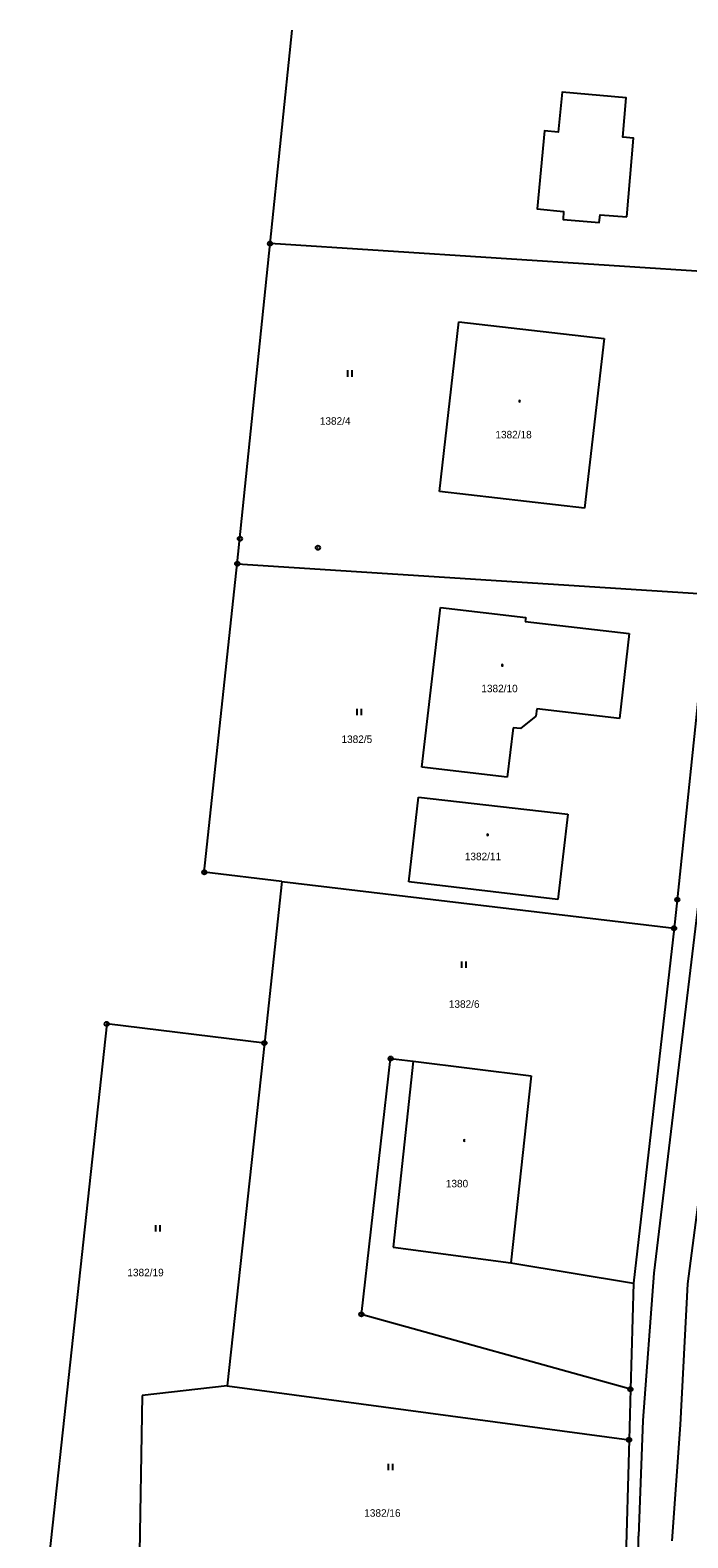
# Model space of a CAD drawing. Extents: x -454285 to -453563, y -1108687 to -1108249.
# Drawn here: x -454197.6 to -454136.3, y -1108463.6 to -1108323 of the extents above; entities that cross this region are included whole.
import ezdxf

# ---------------------------------------------------------------- set-up
doc = ezdxf.new("R2010")
doc.units = 0
for name, color, linetype in [('1', 7, 'Continuous'), ('14', 7, 'Continuous'), ('15', 7, 'Continuous'), ('2', 7, 'Continuous'), ('23', 7, 'Continuous'), ('25', 7, 'Continuous'), ('28', 7, 'Continuous')]:
    doc.layers.add(name, color=color, linetype=linetype)

# ---------------------------------------------------------------- blocks, each defined once
blk = doc.blocks.new('Z402')
for start, end in [(0, 180), (180, 0)]:
    blk.add_arc((0, 0), 0.15, start, end)
blk = doc.blocks.new('Z105')
for radius in [0.5, 0.01]:
    blk.add_circle((0, 0), radius)
blk = doc.blocks.new('Z3060')
for p, q in [((-0.5, 1.5), (-0.5, 0)), ((0.5, 1.5), (0.5, 0))]:
    blk.add_line(p, q)

msp = doc.modelspace()

# ---------------------------------------------------------------- linework, layer by layer
at = {"layer": '1'}
for p, q in [((-454175.21, -1108342.89), (-454173.16, -1108322.99)), ((-454178.27, -1108372.74), (-454175.21, -1108342.89)), ((-454131.27, -1108345.73), (-454175.21, -1108342.89)), ((-454159.44, -1108365.99), (-454157.62, -1108350.19)), ((-454157.62, -1108350.19), (-454144.08, -1108351.75)), ((-454144.08, -1108351.75), (-454145.93, -1108367.55)), ((-454145.93, -1108367.55), (-454159.44, -1108365.99)), ((-454178.27, -1108372.74), (-454134.34, -1108375.58)), ((-454161.07, -1108391.71), (-454159.33, -1108376.82)), ((-454159.33, -1108376.82), (-454151.39, -1108377.74)), ((-454151.39, -1108377.74), (-454151.44, -1108378.11)), ((-454151.44, -1108378.11), (-454141.75, -1108379.24)), ((-454141.75, -1108379.24), (-454142.65, -1108387.16)), ((-454134.9, -1108381.08), (-454137.27, -1108404.06)), ((-454150.36, -1108386.27), (-454150.44, -1108386.95)), ((-454142.65, -1108387.16), (-454150.36, -1108386.27)), ((-454152.56, -1108388.03), (-454153.12, -1108392.64)), ((-454151.88, -1108388.11), (-454152.56, -1108388.03)), ((-454150.44, -1108386.95), (-454151.88, -1108388.11)), ((-454153.12, -1108392.64), (-454161.07, -1108391.71)), ((-454162.3, -1108402.4), (-454161.37, -1108394.5)), ((-454161.37, -1108394.5), (-454147.47, -1108396.09)), ((-454147.47, -1108396.09), (-454148.4, -1108404.03)), ((-454174.11, -1108402.36), (-454175.74, -1108417.43)), ((-454174.11, -1108402.36), (-454137.57, -1108406.72)), ((-454148.4, -1108404.03), (-454162.3, -1108402.4)), ((-454137.27, -1108404.06), (-454137.57, -1108406.72)), ((-454137.57, -1108406.72), (-454141.36, -1108439.81)), ((-454175.74, -1108417.43), (-454179.21, -1108449.4)), ((-454166.7, -1108442.72), (-454163.98, -1108418.87)), ((-454163.98, -1108418.87), (-454161.87, -1108419.13)), ((-454161.87, -1108419.13), (-454150.9, -1108420.47)), ((-454150.9, -1108420.47), (-454152.78, -1108437.92)), ((-454152.78, -1108437.92), (-454141.36, -1108439.81)), ((-454141.36, -1108439.81), (-454141.64, -1108449.7)), ((-454141.64, -1108449.7), (-454166.7, -1108442.72)), ((-454179.21, -1108449.4), (-454187.14, -1108450.29)), ((-454179.21, -1108449.4), (-454141.77, -1108454.42)), ((-454141.64, -1108449.7), (-454141.77, -1108454.42)), ((-454187.14, -1108450.29), (-454187.48, -1108471.9)), ((-454141.77, -1108454.42), (-454142.11, -1108466.47))]:
    msp.add_line(p, q, dxfattribs=at)
for points in [[(-454141.98, -1108340.4), (-454141.36, -1108333.07), (-454142.36, -1108332.96), (-454142.03, -1108329.3), (-454148.01, -1108328.78), (-454148.37, -1108332.5), (-454149.64, -1108332.37), (-454150.32, -1108339.66), (-454147.86, -1108339.89), (-454147.9, -1108340.63), (-454144.54, -1108340.92), (-454144.47, -1108340.2), (-454141.98, -1108340.4)], [(-454174.11, -1108402.36), (-454181.34, -1108401.5), (-454178.27, -1108372.74)], [(-454175.74, -1108417.43), (-454190.43, -1108415.64), (-454197.57, -1108481.57)]]:
    msp.add_lwpolyline(points, dxfattribs=at)
at = {"layer": '2'}
for p, q in [((-454132.33, -1108379.3), (-454139.45, -1108438.88)), ((-454128.49, -1108379.34), (-454136.31, -1108439.89)), ((-454161.87, -1108419.13), (-454163.75, -1108436.45)), ((-454163.75, -1108436.45), (-454152.78, -1108437.92)), ((-454139.45, -1108438.88), (-454140.49, -1108452.62)), ((-454136.31, -1108439.89), (-454136.99, -1108453.03)), ((-454140.49, -1108452.62), (-454140.89, -1108463.39)), ((-454136.99, -1108453.03), (-454137.79, -1108463.83)), ((-454140.74, -1108473.69), (-454140.89, -1108463.39))]:
    msp.add_line(p, q, dxfattribs=at)

# ---------------------------------------------------------------- block references
at = {"layer": '23', "xscale": 0.4, "yscale": 0.4000000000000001}
for p in [(-454167.79, -1108355.3), (-454166.93, -1108386.86), (-454157.18, -1108410.42), (-454185.69, -1108435.01), (-454164, -1108457.25)]:
    msp.add_blockref('Z3060', p, dxfattribs=at)
at = {"layer": '25', "xscale": 0.4, "yscale": 0.4000000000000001}
for p in [(-454151.95, -1108357.58), (-454153.57, -1108382.2), (-454154.94, -1108398.01), (-454157.11, -1108426.51)]:
    msp.add_blockref('Z402', p, dxfattribs=at)
at = {"layer": '28', "xscale": 0.4, "yscale": 0.4000000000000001}
for p in [(-454175.21, -1108342.89), (-454178.03, -1108370.41), (-454170.76, -1108371.25), (-454178.27, -1108372.74), (-454181.34, -1108401.5), (-454137.27, -1108404.06), (-454137.57, -1108406.72), (-454190.43, -1108415.64), (-454175.74, -1108417.43), (-454163.98, -1108418.87), (-454166.7, -1108442.72), (-454141.64, -1108449.7), (-454141.77, -1108454.42)]:
    msp.add_blockref('Z105', p, dxfattribs=at)

# ---------------------------------------------------------------- texts
at = {"layer": '14'}
for s, p in [('1382/4', (-454170.58, -1108359.78)), ('1382/5', (-454168.56, -1108389.45)), ('1382/6', (-454158.56, -1108414.14)), ('1382/19', (-454188.51, -1108439.17)), ('1382/16', (-454166.44, -1108461.59))]:
    msp.add_text(s, height=0.7, dxfattribs=at).set_placement(p)
at = {"layer": '15'}
for s, p in [('1382/18', (-454154.22, -1108361.05)), ('1382/10', (-454155.53, -1108384.72)), ('1382/11', (-454157.07, -1108400.38)), ('1380', (-454158.84, -1108430.88))]:
    msp.add_text(s, height=0.7, dxfattribs=at).set_placement(p)

doc.saveas('drawing.dxf')
